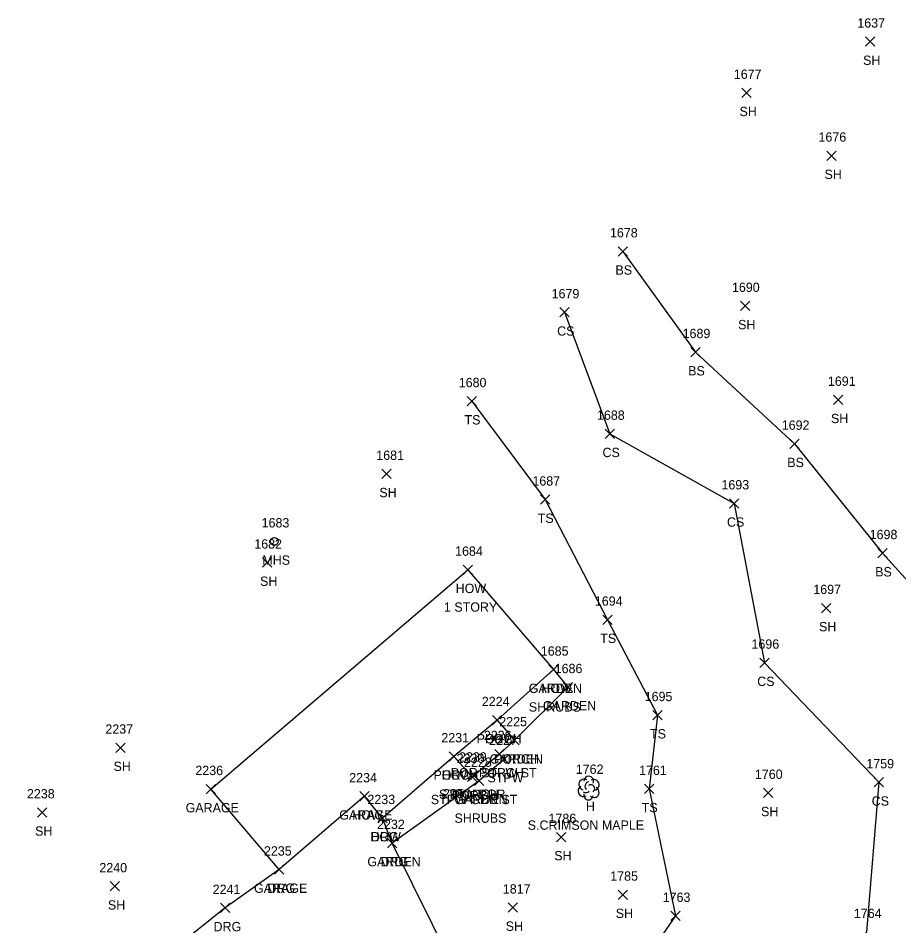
# Model space of a CAD drawing. Extents: x 1520648 to 1523413, y 732854 to 735518.
# Drawn here: x 1522008 to 1522197, y 733961.6 to 734156.3 of the extents above; entities that cross this region are included whole.
import ezdxf

# ---------------------------------------------------------------- set-up
doc = ezdxf.new("R2010")
doc.units = 0
for name, color, linetype in [('L_A', 7, 'Continuous'), ('L_C', 7, 'Continuous'), ('L_I', 7, 'Continuous'), ('L_TIC', 7, 'Continuous'), ('LAPB', 7, 'Continuous'), ('LBC', 7, 'Continuous'), ('LBF', 7, 'Continuous'), ('LELB', 7, 'Continuous'), ('LTD', 7, 'Continuous'), ('R_A', 7, 'Continuous'), ('R_I', 7, 'Continuous'), ('R_TIC', 7, 'Continuous'), ('RDG', 7, 'Continuous'), ('U_A', 7, 'Continuous'), ('U_I', 7, 'Continuous'), ('USMH', 7, 'Continuous')]:
    doc.layers.add(name, color=color, linetype=linetype)

msp = doc.modelspace()

# ---------------------------------------------------------------- linework, layer by layer
at = {"layer": 'L_TIC'}
for points in [[(1522189.86, 734150.27), (1522191.86, 734152.27)], [(1522191.86, 734150.27), (1522189.86, 734152.27)], [(1522163.35, 734139.28), (1522165.35, 734141.28)], [(1522165.35, 734139.28), (1522163.35, 734141.28)], [(1522181.59, 734125.8), (1522183.59, 734127.8)], [(1522183.59, 734125.8), (1522181.59, 734127.8)], [(1522136.78, 734105.28), (1522138.78, 734107.28)], [(1522138.78, 734105.28), (1522136.78, 734107.28)], [(1522163.05, 734093.57), (1522165.05, 734095.57)], [(1522165.05, 734093.57), (1522163.05, 734095.57)], [(1522124.27, 734092.2), (1522126.27, 734094.2)], [(1522126.27, 734092.2), (1522124.27, 734094.2)], [(1522152.38, 734083.66), (1522154.38, 734085.66)], [(1522154.38, 734083.66), (1522152.38, 734085.66)], [(1522104.42, 734073.14), (1522106.42, 734075.14)], [(1522106.42, 734073.14), (1522104.42, 734075.14)], [(1522182.99, 734073.43), (1522184.99, 734075.43)], [(1522184.99, 734073.43), (1522182.99, 734075.43)], [(1522134, 734066.14), (1522136, 734068.14)], [(1522136, 734066.14), (1522134, 734068.14)], [(1522173.64, 734064), (1522175.64, 734066)], [(1522175.64, 734064), (1522173.64, 734066)], [(1522086.06, 734057.54), (1522088.06, 734059.54)], [(1522088.06, 734057.54), (1522086.06, 734059.54)], [(1522120.13, 734052.03), (1522122.13, 734054.03)], [(1522122.13, 734052.03), (1522120.13, 734054.03)], [(1522160.7, 734051.21), (1522162.7, 734053.21)], [(1522162.7, 734051.21), (1522160.7, 734053.21)], [(1522192.51, 734040.54), (1522194.51, 734042.54)], [(1522194.51, 734040.54), (1522192.51, 734042.54)], [(1522060.46, 734038.52), (1522062.46, 734040.52)], [(1522062.46, 734038.52), (1522060.46, 734040.52)], [(1522103.54, 734036.98), (1522105.54, 734038.98)], [(1522105.54, 734036.98), (1522103.54, 734038.98)], [(1522103.54, 734036.98), (1522105.54, 734038.98)], [(1522105.54, 734036.98), (1522103.54, 734038.98)], [(1522180.41, 734028.77), (1522182.41, 734030.77)], [(1522182.41, 734028.77), (1522180.41, 734030.77)], [(1522133.54, 734026.27), (1522135.54, 734028.27)], [(1522135.54, 734026.27), (1522133.54, 734028.27)], [(1522167.2, 734017.04), (1522169.2, 734019.04)], [(1522169.2, 734017.04), (1522167.2, 734019.04)], [(1522121.94, 734015.55), (1522123.94, 734017.55)], [(1522123.94, 734015.55), (1522121.94, 734017.55)], [(1522121.94, 734015.55), (1522123.94, 734017.55)], [(1522123.94, 734015.55), (1522121.94, 734017.55)], [(1522124.97, 734011.8), (1522126.97, 734013.8)], [(1522126.97, 734011.8), (1522124.97, 734013.8)], [(1522109.8, 734004.72), (1522111.8, 734006.72)], [(1522111.8, 734004.72), (1522109.8, 734006.72)], [(1522109.8, 734004.72), (1522111.8, 734006.72)], [(1522111.8, 734004.72), (1522109.8, 734006.72)], [(1522144.23, 734005.79), (1522146.23, 734007.79)], [(1522146.23, 734005.79), (1522144.23, 734007.79)], [(1522029.02, 733998.81), (1522031.02, 734000.81)], [(1522031.02, 733998.81), (1522029.02, 734000.81)], [(1522113.54, 734000.4), (1522115.54, 734002.4)], [(1522115.54, 734000.4), (1522113.54, 734002.4)], [(1522113.54, 734000.4), (1522115.54, 734002.4)], [(1522115.54, 734000.4), (1522113.54, 734002.4)], [(1522100.54, 733996.95), (1522102.54, 733998.95)], [(1522102.54, 733996.95), (1522100.54, 733998.95)], [(1522100.54, 733996.95), (1522102.54, 733998.95)], [(1522102.54, 733996.95), (1522100.54, 733998.95)], [(1522110.3, 733997.44), (1522112.3, 733999.44)], [(1522112.3, 733997.44), (1522110.3, 733999.44)], [(1522110.3, 733997.44), (1522112.3, 733999.44)], [(1522112.3, 733997.44), (1522110.3, 733999.44)], [(1522111.37, 733996.38), (1522113.37, 733998.38)], [(1522113.37, 733996.38), (1522111.37, 733998.38)], [(1522104.48, 733992.54), (1522106.48, 733994.54)], [(1522106.48, 733992.54), (1522104.48, 733994.54)], [(1522104.91, 733992.83), (1522106.91, 733994.83)], [(1522106.91, 733992.83), (1522104.91, 733994.83)], [(1522104.91, 733992.83), (1522106.91, 733994.83)], [(1522106.91, 733992.83), (1522104.91, 733994.83)], [(1522105.99, 733991.7), (1522107.99, 733993.7)], [(1522107.99, 733991.7), (1522105.99, 733993.7)], [(1522105.99, 733991.7), (1522107.99, 733993.7)], [(1522107.99, 733991.7), (1522105.99, 733993.7)], [(1522191.75, 733991.38), (1522193.75, 733993.38)], [(1522193.75, 733991.38), (1522191.75, 733993.38)], [(1522048.38, 733989.93), (1522050.38, 733991.93)], [(1522050.38, 733989.93), (1522048.38, 733991.93)], [(1522142.45, 733989.96), (1522144.45, 733991.96)], [(1522144.45, 733989.96), (1522142.45, 733991.96)], [(1522167.97, 733989.12), (1522169.97, 733991.12)], [(1522169.97, 733989.12), (1522167.97, 733991.12)], [(1522081.34, 733988.38), (1522083.34, 733990.38)], [(1522083.34, 733988.38), (1522081.34, 733990.38)], [(1522081.34, 733988.38), (1522083.34, 733990.38)], [(1522083.34, 733988.38), (1522081.34, 733990.38)], [(1522012.19, 733984.93), (1522014.19, 733986.93)], [(1522014.19, 733984.93), (1522012.19, 733986.93)], [(1522085.25, 733983.71), (1522087.25, 733985.71)], [(1522087.25, 733983.71), (1522085.25, 733985.71)], [(1522123.6, 733979.65), (1522125.6, 733981.65)], [(1522125.6, 733979.65), (1522123.6, 733981.65)], [(1522087.31, 733978.36), (1522089.31, 733980.36)], [(1522089.31, 733978.36), (1522087.31, 733980.36)], [(1522063.05, 733972.67), (1522065.05, 733974.67)], [(1522065.05, 733972.67), (1522063.05, 733974.67)], [(1522027.81, 733969.08), (1522029.81, 733971.08)], [(1522029.81, 733969.08), (1522027.81, 733971.08)], [(1522136.79, 733967.28), (1522138.79, 733969.28)], [(1522138.79, 733967.28), (1522136.79, 733969.28)], [(1522113.18, 733964.52), (1522115.18, 733966.52)], [(1522115.18, 733964.52), (1522113.18, 733966.52)], [(1522148.1, 733962.73), (1522150.1, 733964.73)], [(1522150.1, 733962.73), (1522148.1, 733964.73)]]:
    msp.add_lwpolyline(points, dxfattribs=at)
at = {"layer": 'LAPB'}
for points in [[(1522122.94, 734016.55), (1522125.97, 734012.8), (1522114.54, 734001.4)], [(1522106.99, 733992.7), (1522088.31, 733979.36)]]:
    msp.add_lwpolyline(points, dxfattribs=at)
at = {"layer": 'LBC'}
for points in [[(1522049.38, 733990.93), (1522104.54, 734037.98)], [(1522104.54, 734037.98), (1522122.94, 734016.55), (1522110.8, 734005.72), (1522101.54, 733997.95), (1522086.25, 733984.71), (1522082.34, 733989.38)], [(1522082.34, 733989.38), (1522064.05, 733973.67), (1522049.38, 733990.93)]]:
    msp.add_lwpolyline(points, dxfattribs=at)
at = {"layer": 'LBF'}
for points in [[(1522110.8, 734005.72), (1522114.54, 734001.4), (1522111.3, 733998.44), (1522105.91, 733993.83), (1522105.48, 733993.54), (1522101.54, 733997.95)], [(1522111.3, 733998.44), (1522112.37, 733997.38), (1522106.99, 733992.7), (1522105.91, 733993.83)]]:
    msp.add_lwpolyline(points, dxfattribs=at)
at = {"layer": 'LELB'}
for points in [[(1522137.78, 734106.28), (1522153.38, 734084.66), (1522174.64, 734065), (1522193.51, 734041.54), (1522209.42, 734024)], [(1522125.27, 734093.2), (1522135, 734067.14), (1522161.7, 734052.21), (1522168.2, 734018.04), (1522192.75, 733992.38), (1522190.12, 733960.27), (1522167.92, 733938.99)], [(1522105.42, 734074.14), (1522121.13, 734053.03), (1522134.54, 734027.27), (1522145.23, 734006.79), (1522143.45, 733990.96), (1522149.1, 733963.73), (1522135.66, 733944.27), (1522137.65, 733917.42)]]:
    msp.add_lwpolyline(points, dxfattribs=at)
at = {"layer": 'LTD'}
msp.add_line((1522130.44, 733991.2), (1522130.44, 733991.2), dxfattribs=at)
msp.add_line((1522130.44, 733991.2), (1522130.44, 733991.2), dxfattribs=at)
msp.add_arc((1522130.49, 733992.63), 1.05, 335.5272, 180.9563, dxfattribs=at)
for centre, major_axis, ratio, start_param, end_param in [((1522129.65, 733991.86), (1.21, -0.51), 0.895232, 1.570796, 4.712389), ((1522131.48, 733991.78), (-1.14, -0.48), 0.949671, 1.570796, 4.712389), ((1522129.36, 733990.49), (0.58, -1.04), 0.959034, 3.141593, 6.283185), ((1522130.23, 733991.66), (-0.208, -0.792), 0.645439, 3.141593, 6.283185), ((1522130.94, 733991.03), (-0.5, 0.667), 0.989748, 3.141593, 6.283185), ((1522131.44, 733990.36), (-1.09, 0.79), 0.841452, 1.570796, 4.712389), ((1522130.44, 733989.7), (0.26, 1.06), 0.942809, 1.570796, 4.712389), ((1522129.98, 733990.45), (-0.625, -0.083), 0.423636, 0, 3.141593)]:
    msp.add_ellipse(centre, major_axis=major_axis, ratio=ratio, start_param=start_param, end_param=end_param, dxfattribs=at)
at = {"layer": 'R_TIC'}
for points in [[(1522085.25, 733983.71), (1522087.25, 733985.71)], [(1522087.25, 733983.71), (1522085.25, 733985.71)], [(1522087.31, 733978.36), (1522089.31, 733980.36)], [(1522089.31, 733978.36), (1522087.31, 733980.36)], [(1522063.05, 733972.67), (1522065.05, 733974.67)], [(1522065.05, 733972.67), (1522063.05, 733974.67)], [(1522051.48, 733964.43), (1522053.48, 733966.43)], [(1522053.48, 733964.43), (1522051.48, 733966.43)]]:
    msp.add_lwpolyline(points, dxfattribs=at)
at = {"layer": 'RDG'}
for points in [[(1522154.25, 733883.34), (1522147.27, 733883.63), (1522138.42, 733892.63), (1522124.65, 733910.85), (1522111.52, 733931.27), (1522101.35, 733953.08), (1522088.31, 733979.36), (1522086.25, 733984.71)], [(1522064.05, 733973.67), (1522052.48, 733965.43), (1522041.2, 733956.46), (1522028.39, 733947.51), (1522016.83, 733950.15), (1522008.04, 733950.11)]]:
    msp.add_lwpolyline(points, dxfattribs=at)
at = {"layer": 'USMH'}
for p, q in [((1522063.03, 734044.05), (1522063.03, 734044.05)), ((1522063.87, 734044.05), (1522063.87, 734044.05))]:
    msp.add_line(p, q, dxfattribs=at)
msp.add_circle((1522063.03, 734044.05), 0.833, dxfattribs=at)

# ---------------------------------------------------------------- texts
at = {"layer": 'L_A'}
for s, p in [('SH', (1522189.35, 734146.27)), ('SH', (1522162.84, 734135.28)), ('SH', (1522181.08, 734121.8)), ('BS', (1522136.22, 734101.28)), ('SH', (1522162.54, 734089.57)), ('CS', (1522123.71, 734088.2)), ('BS', (1522151.82, 734079.66)), ('TS', (1522103.83, 734069.14)), ('SH', (1522182.47, 734069.43)), ('CS', (1522133.44, 734062.14)), ('BS', (1522173.08, 734060)), ('SH', (1522085.55, 734053.54)), ('TS', (1522119.54, 734048.03)), ('CS', (1522160.15, 734047.21)), ('BS', (1522191.95, 734036.54)), ('SH', (1522059.95, 734034.52)), ('HOW', (1522101.93, 734032.98)), ('HOW', (1522101.93, 734032.98)), ('SH', (1522179.9, 734024.77)), ('TS', (1522132.95, 734022.27)), ('CS', (1522166.64, 734013.04)), ('GARDEN', (1522117.61, 734011.55)), ('HOW', (1522120.32, 734011.55)), ('GARDEN', (1522120.64, 734007.8)), ('PORCH', (1522106.43, 734000.72)), ('HOW', (1522108.19, 734000.72)), ('TS', (1522143.64, 734001.79)), ('GARDEN', (1522109.21, 733996.4)), ('PORCH', (1522110.16, 733996.4)), ('SH', (1522028.51, 733994.81)), ('PORCH', (1522097.17, 733992.95)), ('HOW', (1522098.93, 733992.95)), ('POR STPW ST', (1522100.88, 733993.44)), ('PORCH', (1522106.92, 733993.44)), ('STPW', (1522108.76, 733992.38)), ('STPW GDN ST', (1522096.6, 733987.7)), ('STPW POR', (1522098.35, 733988.83)), ('PORCH', (1522101.1, 733988.54)), ('PORCH', (1522101.53, 733988.83)), ('GARDEN', (1522101.66, 733987.7)), ('CS', (1522191.2, 733987.38)), ('GARAGE', (1522043.98, 733985.93)), ('H', (1522129.87, 733986.2)), ('TS', (1522141.86, 733985.96)), ('GARAGE', (1522076.94, 733984.38)), ('HOW', (1522079.73, 733984.38)), ('SH', (1522167.46, 733985.12)), ('SH', (1522011.68, 733980.93)), ('HOW', (1522083.64, 733979.71)), ('SH', (1522123.09, 733975.65)), ('GARDEN', (1522082.98, 733974.36)), ('GARAGE', (1522058.65, 733968.67)), ('SH', (1522027.3, 733965.08)), ('SH', (1522136.28, 733963.28)), ('SH', (1522112.67, 733960.52))]:
    msp.add_text(s, height=2, dxfattribs=at).set_placement(p)
at = {"layer": 'L_C'}
for s, p in [('1 STORY', (1522099.41, 734028.98)), ('1 STORY', (1522099.41, 734028.98)), ('SHRUBS', (1522117.63, 734007.55)), ('295', (1522099.18, 733988.95)), ('SHRUBS', (1522101.68, 733983.7)), ('S.CRIMSON MAPLE', (1522117.4, 733982.2))]:
    msp.add_text(s, height=2, dxfattribs=at).set_placement(p)
at = {"layer": 'L_I'}
for s, p in [('1637', (1522188.12, 734154.27)), ('1677', (1522161.61, 734143.28)), ('1676', (1522179.79, 734129.8)), ('1678', (1522135.04, 734109.28)), ('1679', (1522122.52, 734096.2)), ('1690', (1522161.22, 734097.57)), ('1689', (1522150.63, 734087.66)), ('1680', (1522102.59, 734077.14)), ('1691', (1522181.81, 734077.43)), ('1688', (1522132.26, 734070.14)), ('1692', (1522171.9, 734068)), ('1681', (1522084.89, 734061.54)), ('1687', (1522118.39, 734056.03)), ('1693', (1522158.96, 734055.21)), ('1698', (1522190.77, 734044.54)), ('1682', (1522058.72, 734042.52)), ('1684', (1522101.8, 734040.98)), ('1684', (1522101.8, 734040.98)), ('1697', (1522178.67, 734032.77)), ('1694', (1522131.8, 734030.27)), ('1696', (1522165.41, 734021.04)), ('1685', (1522120.2, 734019.55)), ('1685', (1522120.2, 734019.55)), ('1686', (1522123.18, 734015.8)), ('2224', (1522107.54, 734008.72)), ('2224', (1522107.54, 734008.72)), ('1695', (1522142.49, 734009.79)), ('2237', (1522026.76, 734002.81)), ('2225', (1522111.28, 734004.4)), ('2225', (1522111.28, 734004.4)), ('2231', (1522098.85, 734000.95)), ('2231', (1522098.85, 734000.95)), ('2226', (1522107.98, 734001.44)), ('2226', (1522107.98, 734001.44)), ('2227', (1522109.11, 734000.38)), ('2229', (1522102.64, 733996.83)), ('2229', (1522102.64, 733996.83)), ('2230', (1522102.13, 733996.54)), ('2228', (1522103.73, 733995.7)), ('2228', (1522103.73, 733995.7)), ('1759', (1522190.05, 733995.38)), ('2236', (1522046.07, 733993.93)), ('1762', (1522127.7, 733994.2)), ('1761', (1522141.28, 733993.96)), ('1760', (1522166.14, 733993.12)), ('2234', (1522079.08, 733992.38)), ('2234', (1522079.08, 733992.38)), ('2238', (1522009.93, 733988.93)), ('2233', (1522082.99, 733987.71)), ('1786', (1522121.86, 733983.65)), ('2232', (1522085.06, 733982.36)), ('2235', (1522060.79, 733976.67)), ('2240', (1522025.47, 733973.08)), ('1785', (1522135.1, 733971.28)), ('1817', (1522112.05, 733968.52)), ('1763', (1522146.36, 733966.73)), ('1764', (1522187.38, 733963.27))]:
    msp.add_text(s, height=2, dxfattribs=at).set_placement(p)
at = {"layer": 'R_A'}
for p in [(1522083.74, 733979.71), (1522085.8, 733974.36), (1522061.54, 733968.67), (1522049.97, 733960.43)]:
    msp.add_text('DRG', height=2, dxfattribs=at).set_placement(p)
at = {"layer": 'R_I'}
for s, p in [('2233', (1522082.99, 733987.71)), ('2232', (1522085.06, 733982.36)), ('2235', (1522060.79, 733976.67)), ('2241', (1522049.79, 733968.43))]:
    msp.add_text(s, height=2, dxfattribs=at).set_placement(p)
at = {"layer": 'U_A'}
msp.add_text('MHS', height=2, dxfattribs=at).set_placement((1522060.45, 734039.05))
at = {"layer": 'U_I'}
msp.add_text('1683', height=2, dxfattribs=at).set_placement((1522060.29, 734047.05))

doc.saveas('drawing.dxf')
